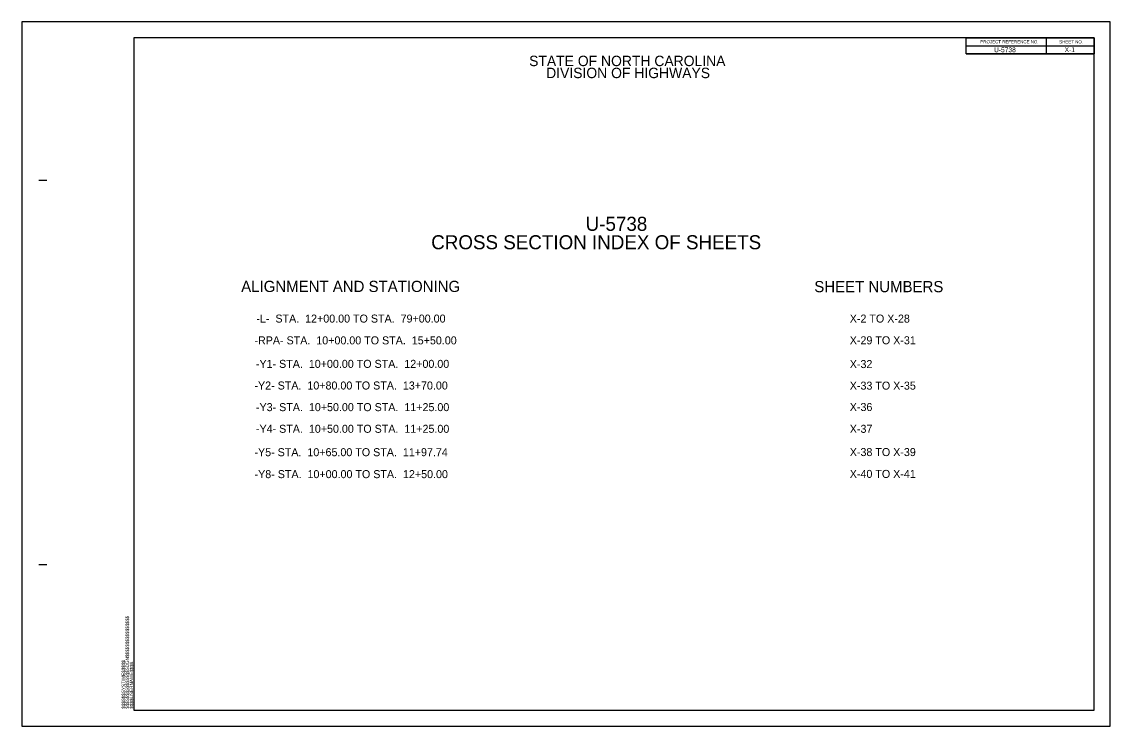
# Model space of a CAD drawing. Extents: x 573852.9 to 573886.9, y -53297.7 to -53275.7.
import ezdxf

# ---------------------------------------------------------------- set-up
doc = ezdxf.new("R2010")
doc.units = 0
for name, color, linetype in [('Sheet Data Field CELL', 7, 'Continuous'), ('Sheet Plot Border Outside CELL', 7, 'Continuous'), ('Sheet Summary CELL', 7, 'Continuous')]:
    doc.layers.add(name, color=color, linetype=linetype)

msp = doc.modelspace()

# ---------------------------------------------------------------- linework, layer by layer
at = {"layer": 'Sheet Plot Border Outside CELL'}
msp.add_lwpolyline([(573852.921, -53297.659), (573886.921, -53297.659), (573886.921, -53275.659), (573852.921, -53275.659)], close=True, dxfattribs=at)
at = {"layer": 'Sheet Summary CELL'}
for p, q in [((573856.421, -53276.159), (573856.421, -53276.968)), ((573884.921, -53276.16), (573884.921, -53276.66)), ((573882.42, -53276.41), (573886.421, -53276.41)), ((573882.42, -53276.66), (573886.421, -53276.66)), ((573853.451, -53280.609), (573853.701, -53280.609)), ((573853.451, -53292.609), (573853.701, -53292.609)), ((573856.421, -53297.159), (573856.421, -53297.159)), ((573856.421, -53297.159), (573856.421, -53297.159)), ((573856.421, -53297.159), (573856.421, -53297.159)), ((573856.421, -53297.159), (573856.421, -53297.159)), ((573856.421, -53297.159), (573856.421, -53297.159)), ((573856.421, -53297.159), (573856.421, -53297.159))]:
    msp.add_line(p, q, dxfattribs=at)
for points in [[(573886.421, -53276.159), (573856.421, -53276.159), (573856.421, -53297.159), (573886.421, -53297.159)], [(573882.42, -53276.159), (573886.421, -53276.159), (573886.421, -53276.66), (573882.42, -53276.66)]]:
    msp.add_lwpolyline(points, close=True, dxfattribs=at)
msp.add_lwpolyline([(573859.171, -53297.159), (573859.171, -53297.159)], dxfattribs=at)

# ---------------------------------------------------------------- texts
at = {"layer": 'Sheet Data Field CELL'}
for s, p in [('U-5738', (573883.292, -53276.61)), ('X-1', (573885.497, -53276.604))]:
    msp.add_text(s, height=0.15, dxfattribs=at).set_placement(p)
at = {"layer": 'Sheet Summary CELL'}
for s, height, p in [('PROJECT REFERENCE NO.', 0.1, (573882.864, -53276.333)), ('SHEET NO.', 0.1, (573885.327, -53276.335)), ('STATE OF NORTH CAROLINA', 0.325, (573868.769, -53277.044)), ('DIVISION OF HIGHWAYS', 0.325, (573869.301, -53277.419)), ('U-5738', 0.439, (573870.534, -53282.188)), ('CROSS SECTION INDEX OF SHEETS', 0.439, (573865.71, -53282.763)), ('ALIGNMENT AND STATIONING', 0.35, (573859.775, -53284.098)), ('SHEET NUMBERS', 0.35, (573877.677, -53284.105)), ('-L-  STA.  12+00.00 TO STA.  79+00.00', 0.25, (573860.249, -53285.053)), ('X-2 TO X-28', 0.25, (573878.785, -53285.053)), ('X-29 TO X-31', 0.25, (573878.785, -53285.731)), ('-RPA- STA.  10+00.00 TO STA.  15+50.00', 0.25, (573860.189, -53285.734)), ('-Y1- STA.  10+00.00 TO STA.  12+00.00', 0.25, (573860.234, -53286.467)), ('X-32', 0.25, (573878.785, -53286.474)), ('-Y2- STA.  10+80.00 TO STA.  13+70.00', 0.25, (573860.189, -53287.143)), ('X-33 TO X-35', 0.25, (573878.785, -53287.147)), ('-Y3- STA.  10+50.00 TO STA.  11+25.00', 0.25, (573860.236, -53287.819)), ('X-36', 0.25, (573878.785, -53287.815)), ('-Y4- STA.  10+50.00 TO STA.  11+25.00', 0.25, (573860.236, -53288.495)), ('X-37', 0.25, (573878.785, -53288.496)), ('-Y5- STA.  10+65.00 TO STA.  11+97.74', 0.25, (573860.189, -53289.226)), ('X-38 TO X-39', 0.25, (573878.785, -53289.222)), ('-Y8- STA.  10+00.00 TO STA.  12+50.00', 0.25, (573860.193, -53289.911)), ('X-40 TO X-41', 0.25, (573878.785, -53289.904))]:
    msp.add_text(s, height=height, dxfattribs=at).set_placement(p)
for s, p in [('$$$$$$$$$$$$$$$$DGN$$$$$$$$$$$$$$$$', (573856.268, -53297.112)), ('$$$$$$SYSTIME$$$$$', (573856.147, -53297.112)), ('$$$$USERNAME$$$$', (573856.399, -53297.111))]:
    msp.add_text(s, height=0.105, rotation=90, dxfattribs=at).set_placement(p)

doc.saveas('drawing.dxf')
